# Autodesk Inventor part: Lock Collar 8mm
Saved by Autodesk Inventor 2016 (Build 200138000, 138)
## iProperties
Created: 2015-11
Part Number: Lock Collar 8mm
Material: Generic
Document SubType Name: Modeling
Designer: John
Density: 1 g/cm^3
Appearance: Default
Author: John
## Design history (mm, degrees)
feature "SOLID1"
body "Solid1"
